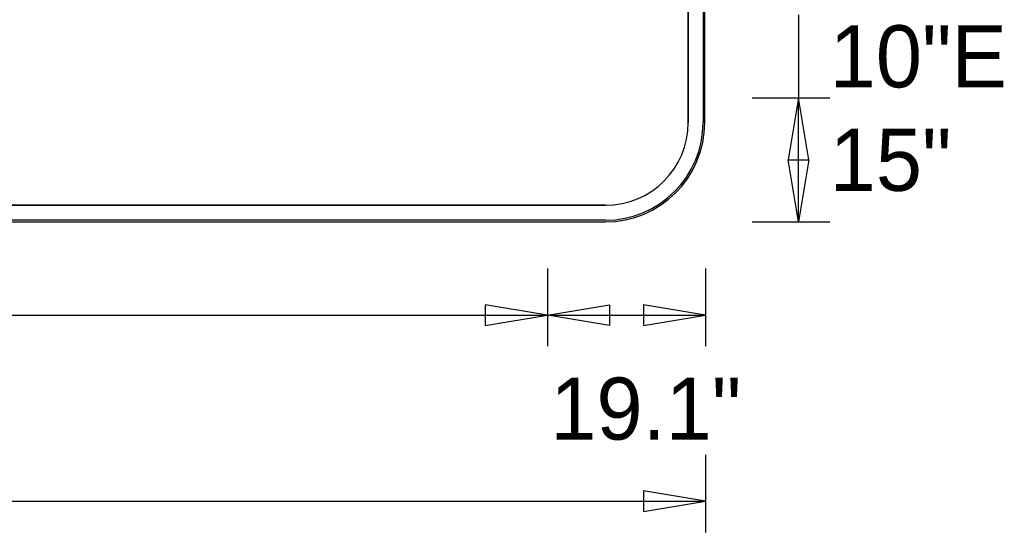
# Model space of a CAD drawing. Extents: x 1806251 to 1809821, y 414895 to 422886.
# Drawn here: x 1809677.968 to 1809679.156, y 415041.405 to 415042.024 of the extents above; entities that cross this region are included whole.
import ezdxf

# ---------------------------------------------------------------- set-up
doc = ezdxf.new("R2010")
doc.units = 0
for name, color, linetype in [('GSBWFILL', 7, 'Continuous'), ('GSCOLORFILL', 7, 'Continuous'), ('GSDIMS', 7, 'Continuous'), ('GSOUTLINE', 7, 'Continuous')]:
    doc.layers.add(name, color=color, linetype=linetype)

msp = doc.modelspace()

# ---------------------------------------------------------------- linework, layer by layer
at = {"layer": 'GSBWFILL'}
for p, q in [((1809678.7751, 415042.8611), (1809678.7751, 415041.9001)), ((1809678.7951, 415041.9001), (1809678.7951, 415042.8611)), ((1809678.6751, 415041.8001), (1809676.5153, 415041.8001)), ((1809676.5153, 415041.7801), (1809678.6751, 415041.7801))]:
    msp.add_line(p, q, dxfattribs=at)
for radius in [0.12, 0.1]:
    msp.add_arc((1809678.6751, 415041.9001), radius, 270, 0, dxfattribs=at)
at = {"layer": 'GSCOLORFILL'}
for p, q in [((1809678.7751, 415042.8611), (1809678.7751, 415041.9001)), ((1809678.7931, 415042.8611), (1809678.7931, 415041.9001)), ((1809678.7951, 415041.9001), (1809678.7951, 415042.8611)), ((1809678.7951, 415041.9001), (1809678.7951, 415042.8611)), ((1809678.7951, 415041.9001), (1809678.7951, 415042.8611)), ((1809678.6751, 415041.8001), (1809676.5153, 415041.8001)), ((1809678.6751, 415041.7821), (1809676.5151, 415041.7821)), ((1809676.5151, 415041.7801), (1809678.6751, 415041.7801)), ((1809676.5151, 415041.7801), (1809678.6751, 415041.7801)), ((1809676.5153, 415041.7801), (1809678.6751, 415041.7801))]:
    msp.add_line(p, q, dxfattribs=at)
for radius in [0.12, 0.12, 0.1, 0.12, 0.118]:
    msp.add_arc((1809678.6751, 415041.9001), radius, 270, 0, dxfattribs=at)
at = {"layer": 'GSDIMS'}
for p, q in [((1809678.9085, 415042.0301), (1809678.9085, 415041.9301)), ((1809678.8522, 415041.9301), (1809678.946, 415041.9301)), ((1809678.8522, 415041.9301), (1809678.946, 415041.9301)), ((1809678.9085, 415041.78), (1809678.9085, 415041.9301)), ((1809678.8522, 415041.78), (1809678.946, 415041.78)), ((1809678.605, 415041.7237), (1809678.605, 415041.63)), ((1809678.605, 415041.7237), (1809678.605, 415041.63)), ((1809678.796, 415041.7237), (1809678.796, 415041.63)), ((1809676.585, 415041.6675), (1809678.605, 415041.6675)), ((1809678.605, 415041.6675), (1809678.796, 415041.6675)), ((1809678.796, 415041.4987), (1809678.796, 415041.405)), ((1809676.395, 415041.4425), (1809678.796, 415041.4425))]:
    msp.add_line(p, q, dxfattribs=at)
for points in [[(1809678.9085, 415041.9301), (1809678.896, 415041.8551), (1809678.921, 415041.8551)], [(1809678.9085, 415041.78), (1809678.896, 415041.855), (1809678.921, 415041.855)], [(1809678.605, 415041.6675), (1809678.53, 415041.68), (1809678.53, 415041.655)], [(1809678.605, 415041.6675), (1809678.68, 415041.68), (1809678.68, 415041.655)], [(1809678.796, 415041.6675), (1809678.721, 415041.68), (1809678.721, 415041.655)], [(1809678.796, 415041.4425), (1809678.721, 415041.455), (1809678.721, 415041.43)]]:
    msp.add_lwpolyline(points, close=True, dxfattribs=at)
at = {"layer": 'GSOUTLINE'}
for p, q in [((1809678.7751, 415041.9001), (1809678.7751, 415042.8611)), ((1809678.7951, 415041.9001), (1809678.7951, 415042.8611)), ((1809676.5151, 415041.8001), (1809678.6751, 415041.8001)), ((1809676.5151, 415041.7801), (1809678.6751, 415041.7801))]:
    msp.add_line(p, q, dxfattribs=at)
for radius in [0.12, 0.1]:
    msp.add_arc((1809678.6751, 415041.9001), radius, 270, 0, dxfattribs=at)

# ---------------------------------------------------------------- texts
at = {"layer": 'GSDIMS'}
for s, p in [('10"E', (1809678.946, 415041.9426)), ('15"', (1809678.946, 415041.8176)), ('19.1"', (1809678.6085, 415041.517))]:
    msp.add_text(s, height=0.075, dxfattribs=at).set_placement(p)

doc.saveas('drawing.dxf')
